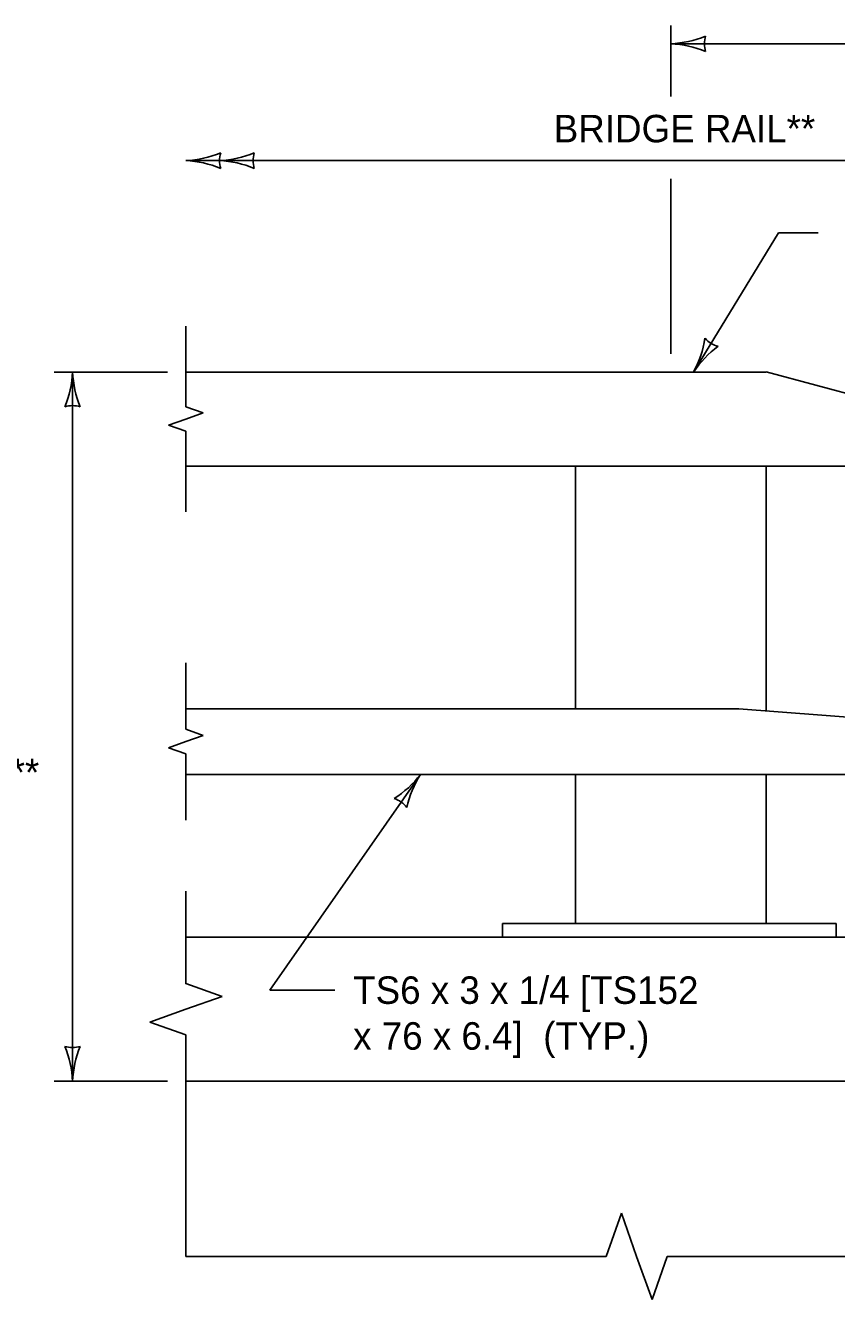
# Model space of a CAD drawing. Extents: x 49991.4 to 50021, y 49987.6 to 50011.4.
# Drawn here: x 50004.991 to 50006.762, y 49992.078 to 49994.86 of the extents above; entities that cross this region are included whole.
import ezdxf

# ---------------------------------------------------------------- set-up
doc = ezdxf.new("R2010")
doc.units = 0
for name, color, linetype in [('Level 1', 7, 'Continuous'), ('Level 2', 7, 'Continuous'), ('Level 3', 7, 'Continuous'), ('Level 4', 7, 'Continuous'), ('Level 6', 7, 'Continuous')]:
    doc.layers.add(name, color=color, linetype=linetype)

msp = doc.modelspace()

# ---------------------------------------------------------------- linework, layer by layer
at = {"layer": 'Level 1'}
for p, q in [((50005.3414, 49994.1032), (50006.608, 49994.1032)), ((50006.954, 49994.0107), (50006.608, 49994.1035)), ((50005.3414, 49993.898), (50006.7232, 49993.898)), ((50006.1916, 49993.3682), (50006.1916, 49993.898)), ((50006.6081, 49993.3634), (50006.6081, 49993.898)), ((50006.7232, 49993.898), (50007.6117, 49993.898)), ((50005.3414, 49993.3681), (50006.5485, 49993.3681)), ((50006.5485, 49993.3681), (50006.9485, 49993.3369)), ((50005.3414, 49993.2246), (50007.6118, 49993.2246)), ((50006.1916, 49993.2246), (50006.1916, 49992.8992)), ((50006.6081, 49993.2246), (50006.6081, 49992.8992)), ((50006.0325, 49992.8991), (50006.0325, 49992.8694)), ((50006.0326, 49992.8992), (50006.7607, 49992.8992)), ((50006.7606, 49992.8991), (50006.7606, 49992.8694)), ((50007.3088, 49992.8695), (50005.3415, 49992.8695)), ((50007.0092, 49992.5549), (50005.3414, 49992.5549))]:
    msp.add_line(p, q, dxfattribs=at)
at = {"layer": 'Level 3'}
for p, q in [((50006.3999, 49994.7046), (50006.3999, 49994.8597)), ((50006.3999, 49994.8197), (50008.9351, 49994.8197)), ((50007.6116, 49994.5646), (50005.3414, 49994.5646)), ((50006.3999, 49994.1432), (50006.3999, 49994.5246)), ((50006.4493, 49994.1032), (50006.6349, 49994.4072)), ((50006.6349, 49994.4072), (50006.7216, 49994.4072)), ((50005.3014, 49994.1032), (50005.0541, 49994.1032)), ((50005.0941, 49992.5549), (50005.0941, 49994.1032)), ((50005.8535, 49993.2246), (50005.5244, 49992.7538)), ((50005.6666, 49992.7538), (50005.5244, 49992.7538)), ((50005.3015, 49992.5549), (50005.0541, 49992.5549))]:
    msp.add_line(p, q, dxfattribs=at)
for centre, radius, start, end in [((50006.3884, 49995.0524), 0.233, 272.8273, 292.0772), ((50006.3907, 49994.5976), 0.2223, 67.456, 87.6395), ((50006.5281, 49994.8197), 0.0548, 162.1388, 197.8612), ((50005.3299, 49994.7973), 0.233, 272.8273, 292.0772), ((50005.3322, 49994.3425), 0.2223, 67.456, 87.6395), ((50005.4033, 49994.7973), 0.233, 272.8273, 292.0772), ((50005.4696, 49994.5646), 0.0548, 162.1388, 197.8612), ((50005.4056, 49994.3425), 0.2223, 67.456, 87.6395), ((50005.543, 49994.5646), 0.0548, 162.1388, 197.8612), ((50006.2549, 49994.2112), 0.2223, 330.9476, 351.1311), ((50006.5161, 49994.2126), 0.0548, 220.7259, 256.4483), ((50006.6419, 49993.9721), 0.233, 126.5099, 145.7598), ((50004.872, 49994.1124), 0.2223, 337.456, 357.6395), ((50005.3268, 49994.1147), 0.233, 182.8273, 202.0772), ((50005.0941, 49993.975), 0.0548, 72.1388, 107.8612), ((50005.6766, 49993.3594), 0.2223, 302.5055, 322.689), ((50006.0508, 49993.1007), 0.233, 147.8768, 167.1267), ((50005.78, 49993.1195), 0.0548, 37.1883, 72.9107), ((50005.0941, 49992.6832), 0.0548, 252.1388, 287.8612), ((50004.8614, 49992.5435), 0.233, 2.8273, 22.0772), ((50005.3163, 49992.5458), 0.2223, 157.456, 177.6395)]:
    msp.add_arc(centre, radius, start, end, dxfattribs=at)
at = {"layer": 'Level 4'}
msp.add_line((50006.3552, 49993.2246), (50006.3552, 49993.2246), dxfattribs=at)
at = {"layer": 'Level 6'}
for p, q in [((50005.3414, 49994.2032), (50005.3414, 49994.0274)), ((50005.3793, 49994.0141), (50005.3414, 49994.0274)), ((50005.3793, 49994.0141), (50005.3414, 49994.0006)), ((50005.3414, 49994.0006), (50005.3035, 49993.9871)), ((50005.3414, 49993.9738), (50005.3035, 49993.9871)), ((50005.3414, 49993.9738), (50005.3414, 49993.798)), ((50005.3415, 49993.4681), (50005.3415, 49993.3232)), ((50005.3794, 49993.3099), (50005.3415, 49993.3232)), ((50005.3415, 49993.2964), (50005.3036, 49993.2829)), ((50005.3415, 49993.2696), (50005.3036, 49993.2829)), ((50005.3794, 49993.3099), (50005.3415, 49993.2964)), ((50005.3415, 49993.2696), (50005.3415, 49993.1246)), ((50005.3415, 49992.9695), (50005.3415, 49992.7679)), ((50005.4206, 49992.7401), (50005.3415, 49992.768)), ((50005.4206, 49992.7401), (50005.3415, 49992.7123)), ((50005.3415, 49992.7123), (50005.2625, 49992.684)), ((50005.3415, 49992.6561), (50005.2625, 49992.684)), ((50005.3415, 49992.6561), (50005.3415, 49992.1726)), ((50005.3415, 49992.6259), (50005.3415, 49992.1726)), ((50006.292, 49992.2669), (50006.2587, 49992.1726)), ((50006.292, 49992.2669), (50006.3252, 49992.1726)), ((50005.3415, 49992.1726), (50006.2587, 49992.1726)), ((50006.3252, 49992.1726), (50006.3589, 49992.0784)), ((50006.3922, 49992.1726), (50006.3589, 49992.0784)), ((50006.3922, 49992.1726), (50007.4088, 49992.1726))]:
    msp.add_line(p, q, dxfattribs=at)

# ---------------------------------------------------------------- texts
at = {"layer": 'Level 2'}
for s, p in [('BRIDGE RAIL**', (50006.1444, 49994.6046)), ('(TYP.)**', (50004.7273, 49993.1991)), ('TS6 x 3 x 1/4 [TS152 ', (50005.7066, 49992.7238)), ('x 76 x 6.4]  (TYP.)', (50005.7066, 49992.6238))]:
    msp.add_text(s, height=0.06, dxfattribs=at).set_placement(p)

doc.saveas('drawing.dxf')
